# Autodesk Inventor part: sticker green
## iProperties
Shininess: 64.0
Length Units: 11269
Angle Units: 11279
Time Units: 11290
Mass Units: 11283
Length Display Precision: 3
Angle Display Precision: 2
Compacted: True
Part Number: sticker green
Document SubType Name: Modeling
Created: 2004-10
Material: Standard
Designer: W. Holzwarth
Manufacturer: Standard
Standards Organization: Custom
Density: 0.0
Volumn: 0.0
Area: 0.0
PropertySet Name: Model Information
Control State: 0
Master: False
Checked Out: False
Author: W. Holzwarth
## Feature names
1. Basis1
